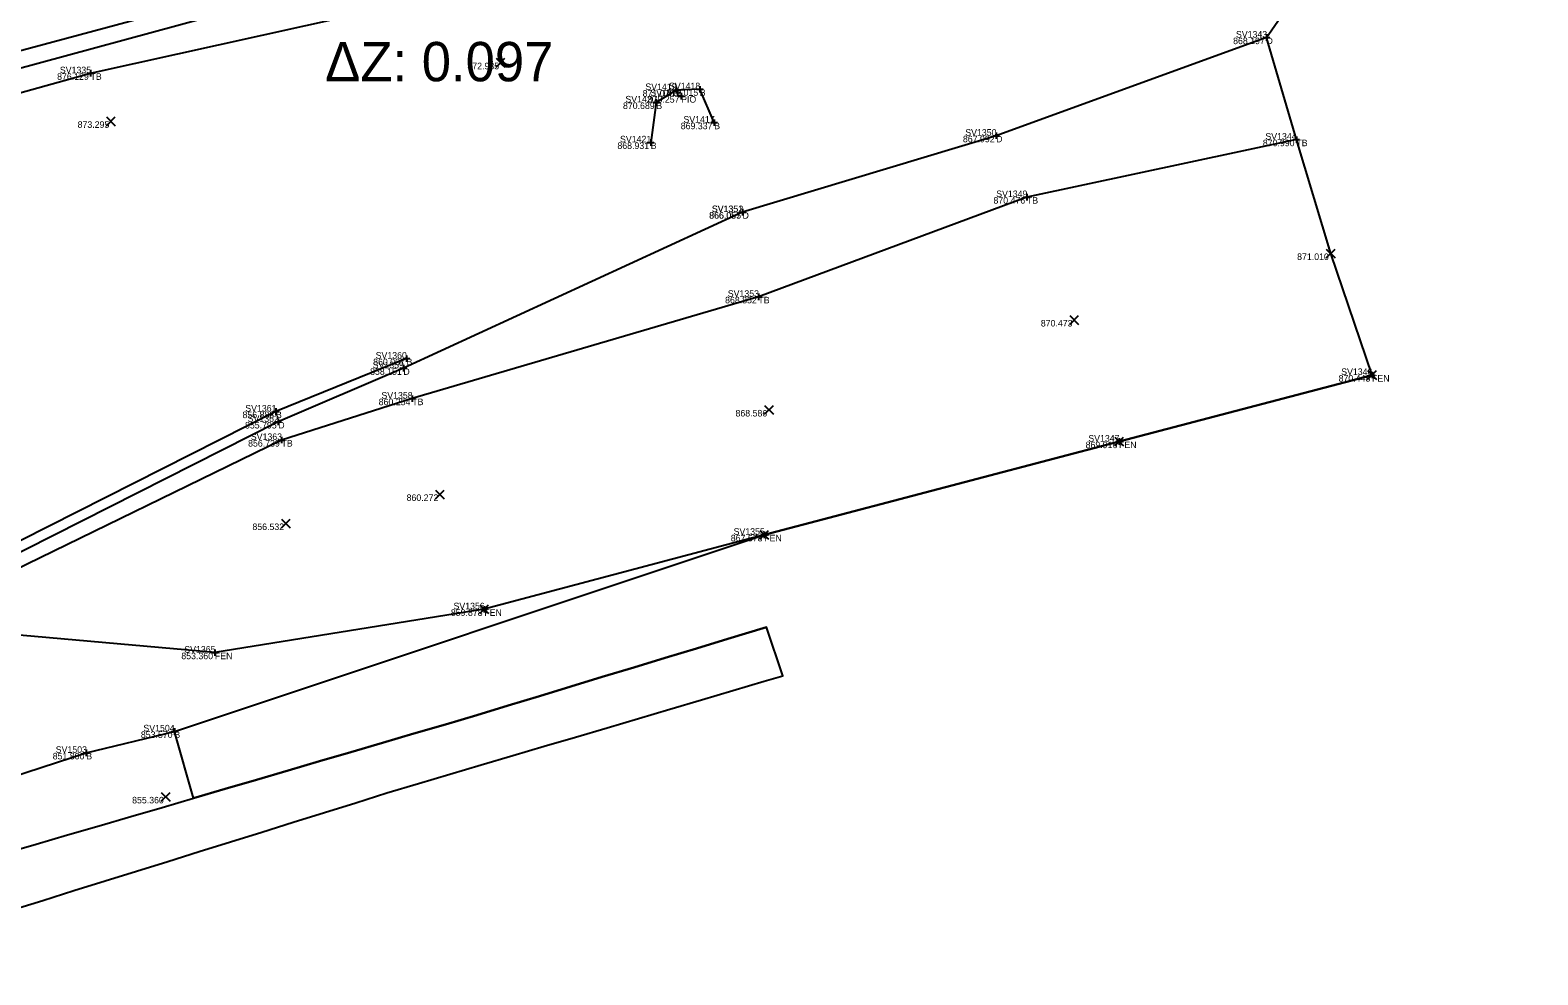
# Model space of a CAD drawing. Extents: x 2125299 to 2129212, y 713100 to 714300.
# Drawn here: x 2128416 to 2128645.9, y 713830 to 713974 of the extents above; entities that cross this region are included whole.
import ezdxf

# ---------------------------------------------------------------- set-up
doc = ezdxf.new("R2010")
doc.units = 0
for name, color, linetype in [('_CIVIL_CONSTRUCTION', 7, 'Continuous'), ('DR_X_Ditch', 7, 'Continuous'), ('DT_X_Terrain_Boundary', 7, 'Continuous'), ('PV_X_EOP', 7, 'Continuous'), ('PV_X_Field_Drive', 7, 'Continuous'), ('RD_X_Fence', 7, 'Continuous'), ('RW_P_Esmt_TMP', 7, 'Continuous'), ('RW_X_CL_100_Cardinal_Points', 7, 'Continuous'), ('RW_X_Esmt_CH', 7, 'Continuous'), ('RW_X_Fee_WL', 7, 'Continuous'), ('SC_Scratch1', 7, 'Continuous'), ('SV_X_Break_Lines', 7, 'Continuous'), ('SV_X_Mon_Cells_Found', 7, 'Continuous'), ('SV_X_Text_Elevation', 7, 'Continuous'), ('SV_X_Top_of_Bank', 7, 'Continuous')]:
    doc.layers.add(name, color=color, linetype=linetype)

msp = doc.modelspace()

# ---------------------------------------------------------------- linework, layer by layer
at = {"layer": 'DR_X_Ditch'}
msp.add_lwpolyline([(2128604.48, 713972.86), (2128563.26, 713957.9), (2128524.58, 713946.25), (2128524.6, 713946.25), (2128472.88, 713922.44), (2128453.8, 713914.26), (2128410.95, 713892.6), (2128396.04, 713888.22), (2128367.5, 713888.62)], dxfattribs=at)
at = {"layer": 'DT_X_Terrain_Boundary'}
msp.add_lwpolyline([(2128413.1, 713839.81), (2128417.88, 713841.3), (2128422.65, 713842.79), (2128427.42, 713844.28), (2128432.2, 713845.76), (2128436.97, 713847.25), (2128441.74, 713848.74), (2128446.51, 713850.23), (2128451.29, 713851.72), (2128456.06, 713853.21), (2128460.83, 713854.7), (2128465.61, 713856.19), (2128470.38, 713857.68), (2128475.17, 713859.13), (2128479.96, 713860.54), (2128484.76, 713861.96), (2128489.55, 713863.38), (2128494.35, 713864.8), (2128499.14, 713866.21), (2128503.94, 713867.63), (2128508.73, 713869.05), (2128513.52, 713870.47), (2128518.32, 713871.88), (2128523.11, 713873.3), (2128527.91, 713874.72), (2128530.74, 713875.55), (2128528.26, 713882.97), (2128522.35, 713881.17), (2128517.57, 713879.72), (2128512.78, 713878.27), (2128508, 713876.82), (2128503.21, 713875.37), (2128498.43, 713873.92), (2128493.64, 713872.46), (2128488.86, 713871.01), (2128484.07, 713869.56), (2128479.28, 713868.13), (2128474.48, 713866.73), (2128469.68, 713865.32), (2128464.89, 713863.92), (2128460.09, 713862.51), (2128455.29, 713861.11), (2128450.49, 713859.7), (2128445.69, 713858.3), (2128440.89, 713856.89), (2128437.96, 713867.07), (2128527.9, 713897.05), (2128582, 713911.26), (2128620.57, 713921.41), (2128614.27, 713939.95), (2128609.03, 713957.3), (2128604.48, 713972.86), (2128645.85, 714032.51)], dxfattribs=at)
at = {"layer": 'PV_X_EOP'}
msp.add_lwpolyline([(2128413.93, 713970.76), (2128423.59, 713973.35), (2128433.25, 713975.95)], dxfattribs=at)
at = {"layer": 'PV_X_Field_Drive'}
for points in [[(2128412.09, 713848.49), (2128416.89, 713849.89), (2128421.69, 713851.29), (2128426.5, 713852.68), (2128431.3, 713854.08), (2128436.09, 713855.49), (2128440.89, 713856.89), (2128445.69, 713858.3), (2128450.49, 713859.7), (2128455.29, 713861.11), (2128460.09, 713862.51), (2128464.89, 713863.92), (2128469.68, 713865.32), (2128474.48, 713866.73), (2128479.28, 713868.13), (2128484.07, 713869.56), (2128488.86, 713871.01), (2128493.64, 713872.46), (2128498.43, 713873.92), (2128503.21, 713875.37), (2128508, 713876.82), (2128512.78, 713878.27), (2128517.57, 713879.72), (2128522.35, 713881.17), (2128528.26, 713882.97)], [(2128413.1, 713839.81), (2128417.88, 713841.3), (2128422.65, 713842.79), (2128427.42, 713844.28), (2128432.2, 713845.76), (2128436.97, 713847.25), (2128441.74, 713848.74), (2128446.51, 713850.23), (2128451.29, 713851.72), (2128456.06, 713853.21), (2128460.83, 713854.7), (2128465.61, 713856.19), (2128470.38, 713857.68), (2128475.17, 713859.13), (2128479.96, 713860.54), (2128484.76, 713861.96), (2128489.55, 713863.38), (2128494.35, 713864.8), (2128499.14, 713866.21), (2128503.94, 713867.63), (2128508.73, 713869.05), (2128513.52, 713870.47), (2128518.32, 713871.88), (2128523.11, 713873.3), (2128527.91, 713874.72), (2128530.74, 713875.55)]]:
    msp.add_lwpolyline(points, dxfattribs=at)
at = {"layer": 'RD_X_Fence'}
msp.add_lwpolyline([(2128620.57, 713921.41), (2128582, 713911.26), (2128527.9, 713897.05), (2128485.22, 713885.69), (2128444.14, 713879.08), (2128410.26, 713882.08), (2128351.04, 713885.85)], dxfattribs=at)
at = {"layer": 'RW_X_CL_100_Cardinal_Points'}
for p, q in [((2128515.23, 713964.44), (2128515.23, 713963.44)), ((2128514.73, 713963.94), (2128515.73, 713963.94)), ((2128515.23, 713963.94), (2128515.23, 713963.94))]:
    msp.add_line(p, q, dxfattribs=at)
at = {"layer": 'SC_Scratch1'}
msp.add_lwpolyline([(2128073.34, 713879.42), (2128205.29, 713913.45), (2128375.42, 713957.63), (2128480.61, 713986.26)], dxfattribs=at)
at = {"layer": 'SV_X_Break_Lines'}
for points in [[(2128520.27, 713959.89), (2128518.07, 713964.98), (2128514.46, 713964.86), (2128511.44, 713962.97), (2128510.59, 713956.88)], [(2128473.36, 713923.91), (2128453.45, 713915.84), (2128410.19, 713893.98), (2128387.41, 713892.53), (2128363.21, 713893.72), (2128345.6, 713896.5), (2128318.82, 713891.26), (2128295.12, 713880.91), (2128274.49, 713885.8), (2128242.12, 713879.2), (2128218.83, 713874.94), (2128184.37, 713862.1), (2128151.55, 713852.79), (2128121.59, 713848.65), (2128121.63, 713848.49), (2128085.29, 713843.49), (2128066.44, 713838.36)], [(2128285.01, 713846.97), (2128304.04, 713841.04), (2128326.03, 713831.97), (2128335.23, 713829.95), (2128351.21, 713834.17), (2128372.65, 713840.36), (2128397.04, 713854.87), (2128424.53, 713863.8), (2128437.96, 713867.07)]]:
    msp.add_lwpolyline(points, dxfattribs=at)
at = {"layer": 'SV_X_Mon_Cells_Found'}
for p, q in [((2128604.48, 713973.36), (2128604.48, 713972.36)), ((2128603.98, 713972.86), (2128604.98, 713972.86)), ((2128604.48, 713972.86), (2128604.48, 713972.86)), ((2128424.67, 713967.42), (2128425.67, 713967.42)), ((2128425.17, 713967.92), (2128425.17, 713966.92)), ((2128425.17, 713967.42), (2128425.17, 713967.42)), ((2128513.96, 713964.86), (2128514.96, 713964.86)), ((2128514.46, 713965.36), (2128514.46, 713964.36)), ((2128514.46, 713964.86), (2128514.46, 713964.86)), ((2128517.57, 713964.98), (2128518.57, 713964.98)), ((2128518.07, 713965.48), (2128518.07, 713964.48)), ((2128518.07, 713964.98), (2128518.07, 713964.98)), ((2128510.94, 713962.97), (2128511.94, 713962.97)), ((2128511.44, 713963.47), (2128511.44, 713962.47)), ((2128511.44, 713962.97), (2128511.44, 713962.97)), ((2128519.77, 713959.89), (2128520.77, 713959.89)), ((2128520.27, 713960.39), (2128520.27, 713959.39)), ((2128520.27, 713959.89), (2128520.27, 713959.89)), ((2128510.59, 713957.38), (2128510.59, 713956.38)), ((2128562.76, 713957.9), (2128563.76, 713957.9)), ((2128563.26, 713958.4), (2128563.26, 713957.4)), ((2128563.26, 713957.9), (2128563.26, 713957.9)), ((2128608.53, 713957.3), (2128609.53, 713957.3)), ((2128609.03, 713957.8), (2128609.03, 713956.8)), ((2128609.03, 713957.3), (2128609.03, 713957.3)), ((2128510.09, 713956.88), (2128511.09, 713956.88)), ((2128510.59, 713956.88), (2128510.59, 713956.88)), ((2128567.45, 713948.54), (2128568.45, 713948.54)), ((2128567.95, 713949.04), (2128567.95, 713948.04)), ((2128567.95, 713948.54), (2128567.95, 713948.54)), ((2128524.08, 713946.25), (2128525.08, 713946.25)), ((2128524.1, 713946.25), (2128525.1, 713946.25)), ((2128524.58, 713946.75), (2128524.58, 713945.75)), ((2128524.58, 713946.25), (2128524.58, 713946.25)), ((2128524.6, 713946.75), (2128524.6, 713945.75)), ((2128524.6, 713946.25), (2128524.6, 713946.25)), ((2128526.51, 713933.34), (2128527.51, 713933.34)), ((2128527.01, 713933.84), (2128527.01, 713932.84)), ((2128527.01, 713933.34), (2128527.01, 713933.34)), ((2128472.86, 713923.91), (2128473.86, 713923.91)), ((2128472.88, 713922.94), (2128472.88, 713921.94)), ((2128473.36, 713924.41), (2128473.36, 713923.41)), ((2128473.36, 713923.91), (2128473.36, 713923.91)), ((2128472.38, 713922.44), (2128473.38, 713922.44)), ((2128472.88, 713922.44), (2128472.88, 713922.44)), ((2128620.07, 713921.41), (2128621.07, 713921.41)), ((2128620.57, 713921.91), (2128620.57, 713920.91)), ((2128620.57, 713921.41), (2128620.57, 713921.41)), ((2128474.23, 713918.31), (2128474.23, 713917.31)), ((2128452.95, 713915.84), (2128453.95, 713915.84)), ((2128453.45, 713916.34), (2128453.45, 713915.34)), ((2128453.45, 713915.84), (2128453.45, 713915.84)), ((2128473.73, 713917.81), (2128474.73, 713917.81)), ((2128474.23, 713917.81), (2128474.23, 713917.81)), ((2128453.3, 713914.26), (2128454.3, 713914.26)), ((2128453.8, 713914.76), (2128453.8, 713913.76)), ((2128453.8, 713914.26), (2128453.8, 713914.26)), ((2128453.79, 713911.5), (2128454.79, 713911.5)), ((2128454.29, 713912), (2128454.29, 713911)), ((2128454.29, 713911.5), (2128454.29, 713911.5)), ((2128581.5, 713911.26), (2128582.5, 713911.26)), ((2128582, 713911.76), (2128582, 713910.76)), ((2128582, 713911.26), (2128582, 713911.26)), ((2128527.9, 713897.55), (2128527.9, 713896.55)), ((2128527.4, 713897.05), (2128528.4, 713897.05)), ((2128527.9, 713897.05), (2128527.9, 713897.05)), ((2128485.22, 713886.19), (2128485.22, 713885.19)), ((2128484.72, 713885.69), (2128485.72, 713885.69)), ((2128485.22, 713885.69), (2128485.22, 713885.69)), ((2128443.64, 713879.08), (2128444.64, 713879.08)), ((2128444.14, 713879.58), (2128444.14, 713878.58)), ((2128444.14, 713879.08), (2128444.14, 713879.08)), ((2128437.96, 713867.57), (2128437.96, 713866.57)), ((2128437.46, 713867.07), (2128438.46, 713867.07)), ((2128437.96, 713867.07), (2128437.96, 713867.07)), ((2128424.03, 713863.8), (2128425.03, 713863.8)), ((2128424.53, 713864.3), (2128424.53, 713863.3)), ((2128424.53, 713863.8), (2128424.53, 713863.8))]:
    msp.add_line(p, q, dxfattribs=at)
at = {"layer": 'SV_X_Text_Elevation'}
for p, q in [((2128487.04, 713968.37), (2128488.37, 713969.7)), ((2128487.04, 713969.7), (2128488.37, 713968.37)), ((2128427.61, 713959.43), (2128428.95, 713960.76)), ((2128427.61, 713960.76), (2128428.95, 713959.43)), ((2128613.6, 713939.28), (2128614.93, 713940.62)), ((2128613.6, 713940.62), (2128614.93, 713939.28)), ((2128574.47, 713929.14), (2128575.8, 713930.47)), ((2128574.47, 713930.47), (2128575.8, 713929.14)), ((2128619.9, 713920.75), (2128621.24, 713922.08)), ((2128619.9, 713922.08), (2128621.24, 713920.75)), ((2128527.96, 713915.42), (2128529.29, 713916.75)), ((2128527.96, 713916.75), (2128529.29, 713915.42)), ((2128581.34, 713910.59), (2128582.67, 713911.93)), ((2128581.34, 713911.93), (2128582.67, 713910.59)), ((2128477.78, 713902.54), (2128479.11, 713903.88)), ((2128477.78, 713903.88), (2128479.11, 713902.54)), ((2128454.27, 713898.11), (2128455.6, 713899.44)), ((2128454.27, 713899.44), (2128455.6, 713898.11)), ((2128527.23, 713896.38), (2128528.57, 713897.72)), ((2128527.23, 713897.72), (2128528.57, 713896.38)), ((2128484.55, 713885.03), (2128485.88, 713886.36)), ((2128484.55, 713886.36), (2128485.88, 713885.03)), ((2128435.97, 713856.43), (2128437.3, 713857.76)), ((2128435.97, 713857.76), (2128437.3, 713856.43))]:
    msp.add_line(p, q, dxfattribs=at)
at = {"layer": 'SV_X_Top_of_Bank'}
for points in [[(2128074.37, 713874.69), (2128142.8, 713890.6), (2128198.94, 713905.19), (2128254.99, 713920.63), (2128306.24, 713935.17), (2128365.05, 713950.7), (2128425.17, 713967.42), (2128484.19, 713980.57), (2128536.73, 713996.44), (2128593.25, 714009.66)], [(2128609.03, 713957.3), (2128567.95, 713948.54), (2128527.01, 713933.34), (2128474.23, 713917.81), (2128454.29, 713911.5), (2128411.32, 713890.53)]]:
    msp.add_lwpolyline(points, dxfattribs=at)

# ---------------------------------------------------------------- texts
at = {"layer": '_CIVIL_CONSTRUCTION'}
msp.add_text('ΔZ: 0.097', height=6, dxfattribs=at).set_placement((2128460.96, 713966.2))
at = {"layer": 'RW_P_Esmt_TMP'}
for s, p in [('D', (2128604.48, 713971.86)), ('TB', (2128425.17, 713966.42)), ('B', (2128514.46, 713963.86)), ('B', (2128518.07, 713963.98)), ('B', (2128511.44, 713961.97)), ('PIO', (2128515.23, 713962.94)), ('B', (2128520.27, 713958.89)), ('D', (2128563.26, 713956.9)), ('TB', (2128609.03, 713956.3)), ('B', (2128510.59, 713955.88)), ('TB', (2128567.95, 713947.54)), ('D', (2128524.58, 713945.25)), ('D', (2128524.6, 713945.25)), ('TB', (2128527.01, 713932.34)), ('B', (2128473.36, 713922.91)), ('D', (2128472.88, 713921.44)), ('FEN', (2128620.57, 713920.41)), ('B', (2128453.45, 713914.84)), ('TB', (2128474.23, 713916.81)), ('D', (2128453.8, 713913.26)), ('TB', (2128454.29, 713910.5)), ('FEN', (2128582, 713910.26)), ('FEN', (2128527.9, 713896.05)), ('FEN', (2128485.22, 713884.69)), ('FEN', (2128444.14, 713878.08)), ('B', (2128437.96, 713866.07)), ('B', (2128424.53, 713862.8))]:
    msp.add_text(s, height=1, dxfattribs=at).set_placement(p)
at = {"layer": 'RW_X_Esmt_CH'}
for s, p in [('SV1343', (2128599.82, 713972.86)), ('SV1335', (2128420.5, 713967.42)), ('SV1419', (2128509.78, 713964.86)), ('SV1416', (2128510.53, 713963.94)), ('SV1418', (2128513.38, 713964.98)), ('SV1420', (2128506.73, 713962.97)), ('SV1417', (2128515.58, 713959.89)), ('SV1421', (2128505.91, 713956.88)), ('SV1350', (2128558.55, 713957.9)), ('SV1344', (2128604.31, 713957.3)), ('SV1349', (2128563.27, 713948.54)), ('SV1351', (2128519.9, 713946.25)), ('SV1352', (2128519.93, 713946.25)), ('SV1353', (2128522.34, 713933.34)), ('SV1359', (2128468.2, 713922.44)), ('SV1360', (2128468.65, 713923.91)), ('SV1346', (2128615.87, 713921.41)), ('SV1358', (2128469.53, 713917.81)), ('SV1361', (2128448.77, 713915.84)), ('SV1362', (2128449.13, 713914.26)), ('SV1363', (2128449.62, 713911.5)), ('SV1347', (2128577.31, 713911.26)), ('SV1355', (2128523.23, 713897.05)), ('SV1356', (2128480.52, 713885.69)), ('SV1365', (2128439.47, 713879.08)), ('SV1504', (2128433.24, 713867.07)), ('SV1503', (2128419.87, 713863.8))]:
    msp.add_text(s, height=1, dxfattribs=at).set_placement(p)
at = {"layer": 'RW_X_Fee_WL'}
for s, p in [('868.197', (2128599.39, 713971.86)), ('872.935', (2128482.64, 713968.03)), ('876.129', (2128420.08, 713966.42)), ('871.076', (2128509.36, 713963.86)), ('871.015', (2128513, 713963.98)), ('870.689', (2128506.36, 713961.97)), ('870.257', (2128510.14, 713962.94)), ('873.295', (2128423.21, 713959.1)), ('869.337', (2128515.17, 713958.89)), ('867.992', (2128558.19, 713956.9)), ('870.990', (2128603.92, 713956.3)), ('868.931', (2128505.51, 713955.88)), ('870.476', (2128562.85, 713947.54)), ('866.057', (2128519.49, 713945.25)), ('866.055', (2128519.53, 713945.25)), ('871.010', (2128609.15, 713938.95)), ('868.852', (2128521.93, 713932.34)), ('870.473', (2128570.07, 713928.81)), ('860.007', (2128468.27, 713922.91)), ('858.151', (2128467.8, 713921.44)), ('870.448', (2128615.47, 713920.41)), ('870.448', (2128615.47, 713920.41)), ('856.888', (2128448.35, 713914.84)), ('860.254', (2128469.11, 713916.81)), ('868.586', (2128523.52, 713915.09)), ('855.795', (2128448.73, 713913.26)), ('856.739', (2128449.2, 713910.5)), ('869.916', (2128576.9, 713910.26)), ('869.916', (2128576.9, 713910.26)), ('860.272', (2128473.37, 713902.21)), ('856.532', (2128449.86, 713897.77)), ('867.578', (2128522.8, 713896.05)), ('867.578', (2128522.8, 713896.05)), ('859.878', (2128480.12, 713884.69)), ('859.878', (2128480.12, 713884.69)), ('853.360', (2128439.02, 713878.08)), ('853.570', (2128432.85, 713866.07)), ('851.800', (2128419.41, 713862.8)), ('855.360', (2128431.52, 713856.09))]:
    msp.add_text(s, height=1, dxfattribs=at).set_placement(p)

doc.saveas('drawing.dxf')
